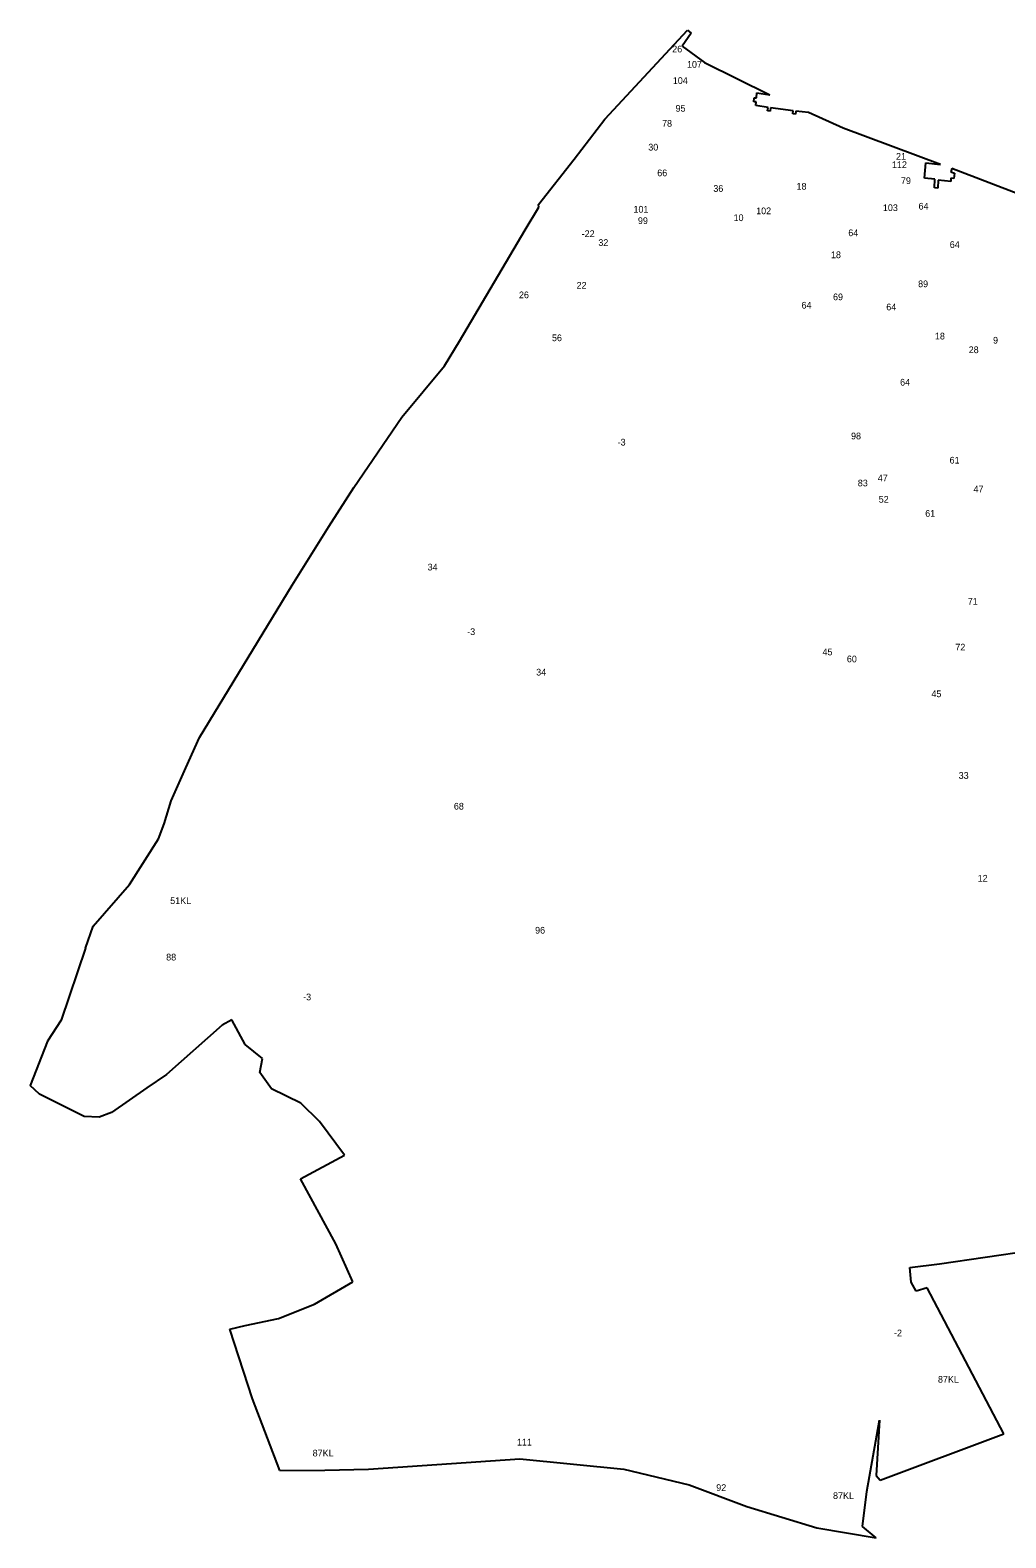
# Model space of a CAD drawing. Extents: x -777600 to -775967, y -979064 to -977637.
# Drawn here: x -777600 to -776799, y -979064 to -977827 of the extents above; entities that cross this region are included whole.
import ezdxf

# ---------------------------------------------------------------- set-up
doc = ezdxf.new("R2010")
doc.units = 0
doc.layers.add('Vrstva 13', color=7, linetype='Continuous')
doc.layers.add('Vrstva 24', color=7, linetype='Continuous')

msp = doc.modelspace()

# ---------------------------------------------------------------- linework, layer by layer
at = {"layer": 'Vrstva 13'}
for p, q in [((-777128.21, -977900.39), (-777060.47, -977827.36)), ((-777057.36, -977829.73), (-777064.76, -977840.54)), ((-777060.47, -977827.36), (-777057.36, -977829.73)), ((-777064.76, -977840.54), (-777046.55, -977854.02)), ((-777046.55, -977854.02), (-776992.79, -977880.39)), ((-777005.96, -977886.06), (-777005.8, -977882.93)), ((-777005.8, -977882.93), (-777003.72, -977883)), ((-777003.72, -977883), (-777003.44, -977878.77)), ((-777003.44, -977878.77), (-776992.79, -977880.39)), ((-777004.17, -977886.13), (-777005.96, -977886.06)), ((-777004.35, -977889.12), (-777004.17, -977886.13)), ((-776994.39, -977890.78), (-777004.35, -977889.12)), ((-776994.85, -977893.67), (-776994.39, -977890.78)), ((-776992.7, -977893.93), (-776994.85, -977893.67)), ((-776992.25, -977891.03), (-776992.7, -977893.93)), ((-776973.69, -977893.57), (-776992.25, -977891.03)), ((-776974.1, -977896.05), (-776973.69, -977893.57)), ((-776971.9, -977896.28), (-776974.1, -977896.05)), ((-776971.51, -977893.92), (-776971.9, -977896.28)), ((-776961.21, -977894.81), (-776971.51, -977893.92)), ((-776932.69, -977907.71), (-776961.21, -977894.81)), ((-777153.39, -977933.27), (-777128.21, -977900.39)), ((-776852.97, -977937.58), (-776932.69, -977907.71)), ((-777182.59, -977970.45), (-777153.39, -977933.27)), ((-776865.93, -977948.81), (-776865.08, -977936.32)), ((-776865.08, -977936.32), (-776852.97, -977937.58)), ((-776843.52, -977940.91), (-776844.41, -977943.69)), ((-776844.41, -977943.69), (-776841.41, -977944.58)), ((-776785.92, -977963.07), (-776843.52, -977940.91)), ((-776841.41, -977944.58), (-776841.97, -977949.18)), ((-776857.49, -977949.66), (-776865.93, -977948.81)), ((-776857.9, -977956.67), (-776857.49, -977949.66)), ((-776855.23, -977956.85), (-776857.9, -977956.67)), ((-776854.78, -977950.48), (-776855.23, -977956.85)), ((-776844.56, -977951.48), (-776854.78, -977950.48)), ((-776844.34, -977948.77), (-776844.56, -977951.48)), ((-776841.97, -977949.18), (-776844.34, -977948.77)), ((-777193.66, -977991.28), (-777182.3, -977972.64)), ((-777182.3, -977972.64), (-777182.59, -977970.45)), ((-777247.41, -978082.46), (-777193.66, -977991.28)), ((-777259.85, -978102.83), (-777247.41, -978082.46)), ((-777294.8, -978144.9), (-777259.85, -978102.83)), ((-777334.19, -978202.52), (-777294.8, -978144.9)), ((-777354.54, -978234.59), (-777334.19, -978202.52)), ((-777384.75, -978282.62), (-777354.54, -978234.59)), ((-777460.79, -978407.64), (-777384.75, -978282.62)), ((-777471.89, -978432.42), (-777460.79, -978407.64)), ((-777484.07, -978459.49), (-777471.89, -978432.42)), ((-777489.57, -978478.4), (-777484.07, -978459.49)), ((-777494.24, -978490.62), (-777489.57, -978478.4)), ((-777518.08, -978528.25), (-777494.24, -978490.62)), ((-777547.98, -978562.47), (-777518.08, -978528.25)), ((-777554.28, -978580.32), (-777547.98, -978562.47)), ((-777554.28, -978580.32), (-777574.19, -978639.49)), ((-777574.19, -978639.49), (-777585.44, -978656.6)), ((-777442.23, -978643.54), (-777487.72, -978684.01)), ((-777434.23, -978639.28), (-777442.23, -978643.54)), ((-777423.3, -978659.35), (-777434.23, -978639.28)), ((-777585.44, -978656.6), (-777599.62, -978693.04)), ((-777409.16, -978670.98), (-777423.3, -978659.35)), ((-777411.31, -978682.46), (-777409.16, -978670.98)), ((-777487.72, -978684.01), (-777503.97, -978695.05)), ((-777401.68, -978695.72), (-777411.31, -978682.46)), ((-777592.07, -978700.26), (-777599.62, -978693.04)), ((-777503.97, -978695.05), (-777532.77, -978715.3)), ((-777377.55, -978707.5), (-777401.68, -978695.72)), ((-777555.24, -978718.41), (-777592.07, -978700.26)), ((-777362.22, -978722.53), (-777377.55, -978707.5)), ((-777543.02, -978719.15), (-777555.24, -978718.41)), ((-777532.77, -978715.3), (-777543.02, -978719.15)), ((-777341.72, -978750.16), (-777362.22, -978722.53)), ((-777377.92, -978769.56), (-777341.72, -978750.16)), ((-777348.79, -978822.96), (-777377.92, -978769.56)), ((-777334.99, -978854.28), (-777348.79, -978822.96)), ((-776853.81, -978839.38), (-776778.88, -978828.35)), ((-776877.99, -978842.26), (-776853.81, -978839.38)), ((-776876.92, -978854.52), (-776877.99, -978842.26)), ((-777366.3, -978872.5), (-777334.99, -978854.28)), ((-776872.85, -978861.82), (-776876.92, -978854.52)), ((-776863.85, -978859.19), (-776872.85, -978861.82)), ((-776800.84, -978978.78), (-776863.85, -978859.19)), ((-777396.05, -978884.27), (-777366.3, -978872.5)), ((-777423.29, -978889.9), (-777396.05, -978884.27)), ((-777435.87, -978892.86), (-777423.29, -978889.9)), ((-777417.23, -978950.19), (-777435.87, -978892.86)), ((-777394.87, -979008.99), (-777417.23, -978950.19)), ((-776913.29, -979026.28), (-776902.84, -978967.68)), ((-776902.84, -978967.68), (-776905.66, -979013.05)), ((-776902.36, -979016.75), (-776800.84, -978978.78)), ((-777394.87, -979008.99), (-777357.9, -979008.74)), ((-777357.9, -979008.74), (-777321.99, -979007.93)), ((-777321.99, -979007.93), (-777197.9, -978999.41)), ((-777197.9, -978999.41), (-777112.6, -979007.7)), ((-777112.6, -979007.7), (-777059.12, -979020.65)), ((-777059.12, -979020.65), (-777011.66, -979038.42)), ((-776905.66, -979013.05), (-776902.36, -979016.75)), ((-776916.99, -979054.95), (-776913.29, -979026.28)), ((-777011.66, -979038.42), (-776954.27, -979055.9)), ((-776954.27, -979055.9), (-776905.77, -979064.17)), ((-776905.77, -979064.17), (-776916.99, -979054.95))]:
    msp.add_line(p, q, dxfattribs=at)

# ---------------------------------------------------------------- texts
at = {"layer": 'Vrstva 24'}
for s, p in [('26', (-777072.96, -977845.61)), ('107', (-777060.868, -977858.2)), ('104', (-777072.477, -977871.45)), ('95', (-777070.24, -977894.23)), ('78', (-777081.302, -977906.6)), ('30', (-777092.608, -977926.1)), ('21', (-776889.4, -977933.65)), ('66', (-777085.24, -977947.2)), ('112', (-776892.738, -977940.46)), ('36', (-777039.25, -977960.01)), ('18', (-776971.01, -977958.22)), ('79', (-776885.362, -977953.57)), ('103', (-776900.158, -977975.74)), ('64', (-776870.92, -977974.54)), ('101', (-777104.756, -977977.03)), ('99', (-777101.1, -977986.35)), ('10', (-777022.638, -977984.01)), ('102', (-777004.108, -977978.35)), ('-22', (-777147.252, -977997.09)), ('64', (-776928.54, -977996.37)), ('32', (-777133.59, -978004.35)), ('64', (-776845.31, -978005.98)), ('18', (-776942.77, -978014.41)), ('26', (-777198.68, -978047.27)), ('22', (-777151.38, -978039.4)), ('69', (-776941.08, -978048.91)), ('89', (-776871.29, -978038.22)), ('64', (-776966.95, -978055.75)), ('64', (-776897.4, -978057.21)), ('56', (-777171.62, -978082.5)), ('18', (-776857.49, -978081.08)), ('9', (-776809.81, -978084.49)), ('28', (-776829.77, -978092.31)), ('64', (-776886.05, -978118.92)), ('-3', (-777117.752, -978168.11)), ('98', (-776926.29, -978163.02)), ('61', (-776845.459, -978182.88)), ('47', (-776904.411, -978197.56)), ('83', (-776920.74, -978201.6)), ('47', (-776825.831, -978206.58)), ('52', (-776903.58, -978214.99)), ('61', (-776865.489, -978226.52)), ('34', (-777273.6, -978270.58)), ('71', (-776830.53, -978298.69)), ('-3', (-777241.132, -978323.56)), ('45', (-776949.7, -978340.18)), ('60', (-776929.718, -978345.91)), ('72', (-776840.752, -978336.25)), ('34', (-777184.55, -978356.77)), ('45', (-776860.36, -978374.53)), ('33', (-776837.99, -978441.5)), ('68', (-777252.07, -978466.74)), ('12', (-776822.43, -978525.85)), ('51KL', (-777484.75, -978544.21)), ('96', (-777185.44, -978568.48)), ('88', (-777488.05, -978590.53)), ('-3', (-777375.702, -978623.21)), ('-2', (-776891.052, -978898.88)), ('87KL', (-776855.002, -978936.89)), ('111', (-777200.328, -978988.42)), ('87KL', (-777367.912, -978997.39)), ('92', (-777036.86, -979025.69)), ('87KL', (-776941.062, -979032.3))]:
    msp.add_text(s, height=5.5, dxfattribs=at).set_placement(p)

doc.saveas('drawing.dxf')
